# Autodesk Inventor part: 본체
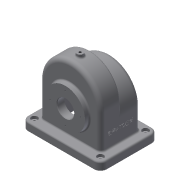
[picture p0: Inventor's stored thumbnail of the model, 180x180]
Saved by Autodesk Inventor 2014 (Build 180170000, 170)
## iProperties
Created: 2017-11
Part Number: 본체
Material: Generic
Document SubType Name: Modeling
Designer: user
Density: 1 g/cm^3
Appearance: Default
Author: user
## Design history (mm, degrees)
sketch "스케치1"
  geometry: L1 (-75, 55)-(75, 55); L2 (75, 55)-(75, -55); L3 (75, -55)-(-75, -55); L4 (-75, -55)-(-75, 55); L5 (-75, 55)-(75, -55); L6 (75, 55)-(-75, -55); 1 further point
  constraints: 12 end point, 2 midpoint, 2 parallel, 1 horizontal, 1 perpendicular
  dimensions: "d0" = 150 distance of L2.end L3.end; "d1" = 110 distance of L1.end L2.end
extrude "돌출1" new body sketch "스케치1" distance "d2" = 15; taper "d3" = 0 deg
sketch "스케치2"
  geometry: L1 (58, 0)-(-58, 0); L2 (-58, 0)-(-58, 80); L3 (-58, 80)-(58, 80); L4 (58, 80)-(58, 0); L5 (58, 0)-(-58, 80); L6 (-58, 0)-(58, 80); L7 (0, 0)-(0, 40); 1 further point
  constraints: 14 end point, 3 midpoint, 3 parallel, 1 horizontal, 1 perpendicular
  dimensions: "d5" = 116 distance of L2.end L3.end; "d6" = 80 distance of L1.end L2.end; "d7" = 40 distance of L7.end L7.start
extrude "돌출2" join sketch "스케치2" distance "d8" = 38; taper "d9" = 0 deg
sketch "스케치3"
  geometry: L1 (-58, 80)-(-58, 15) reference; L2 (0, 0)-(0, 28.5); L3 (58, 0)-(-58, 0); L4 (-58, 0)-(-58, 57); L5 (-58, 57)-(58, 57); L6 (58, 57)-(58, 0); L7 (58, 0)-(-58, 57); L8 (-58, 0)-(58, 57)
  constraints: 14 end point, 3 parallel, 2 midpoint, 1 horizontal, 1 perpendicular
  dimensions: "d10" = 28.5 distance of L2.start L2.end; "d11" = 116 distance of L4.end L5.end; "d12" = 57 distance of L3.end L4.end
extrude "돌출3" join sketch "스케치3" distance "d13" = 38; taper "d14" = 0 deg
sketch "스케치4"
  geometry: L1 (58, 80)-(-58, 80) reference; 2 further points
  constraints: 1 horizontal alignment, 1 midpoint, 2 other
extrude "돌출4" join sketch "스케치4" distance "d15" = 38; taper "d16" = 0 deg
sketch "스케치5"
  geometry: L1 (-58, 57)-(58, 57) reference; L2 (-75, 0)-(75, 0) reference; L3 (-10.724, 0)-(10.724, 0); A1 r 58 centre (0, 57) between (10.724, 0) and (-10.724, 0); 1 further point
  constraints: 3 point on circle, 2 end point, 2 point on line, 1 centre point, 1 collinear, 1 midpoint
extrude "돌출5" join sketch "스케치5" distance "d17" = 38; taper "d18" = 0 deg
sketch "스케치6"
  geometry: L1 (58, 15)-(58, 80) reference; L2 (0, 0)-(0, 65); C1 r 37.5 at (0, 65)
  constraints: 2 end point, 1 centre point, 1 coincident, 1 parallel
  dimensions: "d19" = 65 distance of L2.start L2.end; "d20" = 75 diameter of C1
extrude "돌출6" join sketch "스케치6" distance "d21" = 9; taper "d22" = 0 deg
sketch "스케치7"
  geometry: L1 (-58, 57)-(-58, 15) reference; L2 (0, 0)-(0, 65); C1 r 31 at (0, 65)
  constraints: 2 end point, 1 centre point, 1 coincident, 1 parallel
  dimensions: "d23" = 65 distance of L2.start L2.end; "d24" = 62 diameter of C1
extrude "돌출7" join sketch "스케치7" distance "d25" = 10; taper "d26" = 0 deg
sketch "스케치8"
  geometry: C1 r 37.5 at (0, 0) reference; C2 r 16 at (0, 0); 1 further point
  constraints: 1 centre point, 1 coincident
  dimensions: "d27" = 32 diameter of C2
extrude "돌출8" cut sketch "스케치8" distance "d28" = 95; taper "d29" = 0 deg
sketch "스케치9"
  geometry: L1 (53, -33)-(-53, -33); L2 (-53, -33)-(-53, 33); L3 (-53, 33)-(53, 33); L4 (53, 33)-(53, -33); L5 (53, -33)-(-53, 33); L6 (-53, -33)-(53, 33); 1 further point
  constraints: 12 end point, 2 midpoint, 2 parallel, 1 horizontal, 1 perpendicular
  dimensions: "d30" = 106 distance of L2.end L3.end; "d31" = 66 distance of L1.end L2.end
extrude "돌출9" cut sketch "스케치9" distance "d32" = 57; taper "d33" = 0 deg
sketch "스케치10"
  geometry: L1 (102.5, 47)-(27.5, 47) reference; L2 (57, 33)-(57, -33) reference; L3 (57, -33)-(57, 11.323); L4 (57, -33)-(110, -33); L5 (110, -33)-(110, 5); L6 (110, 5)-(57, 5); 1 further point
  constraints: 8 end point, 2 perpendicular, 2 point on line
  dimensions: "d34" = 53 distance of L2.end L4.end; "d35" = 38 distance of L4.end L5.end; "d36" = 53 distance of L5.end L6.end
revolve "회전1" sketch "스케치10" stored, may be unused: angle "d37" = 90 deg
sketch "스케치11"
  geometry: L1 (80, 38)-(138, 38) reference; L2 (138, 38)-(138, 0) reference; L3 (80, 38)-(85, 38); L4 (80, 33)-(133, 33); L5 (133, 33)-(133, 5); L6 (133, 5)-(80, 5); L7 (80, 33)-(80, 5); 1 further point
  constraints: 10 end point, 2 perpendicular, 1 horizontal, 1 parallel
  dimensions: "d39" = 5 distance of L1.start L4.start; "d41" = 53 distance of L4.start L4.end; "d42" = 28 distance of L4.end L5.end
revolve "회전2" sketch "스케치11" stored, may be unused: angle "d43" = 90 deg
sketch "스케치12"
  geometry: L1 (-53, -33)-(-53, 33) reference; L2 (-53, 33)-(53, 33) reference; L3 (-53, 5)-(-47.749, 5) reference; L4 (47.749, 33)-(47.749, 5) reference; L5 (47.749, 5)-(53, 5) reference; L6 (53, 33)-(53, 5) reference; L7 (47.749, 33)-(53, 33) reference; L8 (-47.749, 5)-(-47.749, 33) reference; L9 (-47.749, 5)-(-47.749, 33) reference; L10 (-53, 33)-(-47.749, 33) reference; L11 (-53, 5)-(-53, 33) reference; L12 (-53, 5)-(-47.749, 5) reference; 1 further point
extrude "돌출10" cut sketch "스케치12" distance "d44" = 80; taper "d45" = 0 deg
sketch "스케치13" dims "d46" = 58
  geometry: C1 r 37.5 at (0, 0) reference; C2 r 1.5 at (0, 29); C3 r 1.5 at (-29, 0); C4 r 1.5 at (0, -29); C5 r 1.5 at (29, 0); 5 further points
  constraints: 4 centre point, 4 coincident, 1 vertical alignment, 11 other
  dimensions: "d47" = 3 diameter of C2; "d50" = 360 deg dimension on point (0, 0) C2.centre (derived)
hole "구멍1" sketch "스케치13" at (0, 29), (-29, 0), (0, -29), (29, 0) diameter "d52" = 2.459; stored, may be unused: countersink angle "d56" = 90 deg, drill point angle "d58" = 118 deg; dims "d53" = 6, "d54" = 4, "d55" = 2, "d57" = 8
sketch "스케치14" dims "d59" = 52
  geometry: C1 r 31 at (0, 0) reference; C2 r 1.5 at (-26, 0); C3 r 1.5 at (0, -26); C4 r 1.5 at (26, 0); C5 r 1.5 at (0, 26); 2 further points
  constraints: 4 centre point, 1 coincident, 1 horizontal alignment, 11 other
  dimensions: "d60" = 3 diameter of C2; "d63" = 360 deg dimension on point (0, 0) C2.centre (derived)
hole "구멍2" sketch "스케치14" at (0, 26), (26, 0), (0, -26), (-26, 0) diameter "d65" = 2.459; stored, may be unused: countersink angle "d69" = 90 deg, drill point angle "d71" = 118 deg; dims "d66" = 6, "d67" = 4, "d68" = 2, "d70" = 8
fillet "모깎기1" dims "d72" = 12
sketch "스케치15"
  geometry: A1 r 12 centre (-63, 43) between (-63, 55) and (-75, 43) reference; A2 r 12 centre (-63, -43) between (-75, -43) and (-63, -55) reference; A3 r 12 centre (63, -43) between (63, -55) and (75, -43) reference; A4 r 12 centre (63, 43) between (75, 43) and (63, 55) reference; 1 further point
hole "구멍3" sketch "스케치15" at (-63, -43), (63, -43), (63, 43), (-63, 43) diameter "d73" = 5; stored, may be unused: countersink angle "d77" = 90 deg, drill point angle "d79" = 118 deg; dims "d74" = 6, "d75" = 12, "d76" = 5, "d78" = 8
node "작업 평면2"
sketch "스케치17"
  geometry: L1 (-58, 38)-(58, 38) reference; L2 (0, 38)-(0, 19); C1 r 6 at (0, 19); 1 further point
  constraints: 2 end point, 1 centre point, 1 coincident, 1 midpoint, 1 perpendicular
  dimensions: "d82" = 19 distance of L2.start L2.end; "d83" = 12 diameter of C1
extrude "돌출11" join sketch "스케치17" stored distance "d84" = 80; taper "d85" = 0 deg
sketch "스케치18"
  geometry: C1 r 6 at (0, 0) reference; 1 further point
hole "구멍4" sketch "스케치18" at (0, 0) diameter "d86" = 4.459; stored, may be unused: countersink angle "d90" = 90 deg, drill point angle "d92" = 118 deg; dims "d87" = 25, "d88" = 12, "d89" = 5, "d91" = 8
fillet "모깎기2" dims "d93" = 3
chamfer "모따기1" distance "d94" = 1; stored, may be unused: second distance "d95" = 2, angle "d96" = 45 deg
fillet "모깎기3" dims "d101" = 8
fillet "모깎기4" dims "d102" = 3
sketch "스케치20"
  geometry: L1 (-35, 23)-(-35, -39) reference; L2 (-40, -57)-(-52, -57) reference; 2 further points
  constraints: 1 other
  dimensions: "d103" = 38 distance from line of point (3, -17) L1; "d104" = 40 distance from line of L2 point (3, -17)
feature "엠보싱2" sketch "스케치20" dims "d0" = 150, "d1" = 110, "d10" = 28.5, "d11" = 116, "d12" = 57, "d105" = 0.5, "d106" = 0
node "솔리드1"
node "투영된 루프1"
node "투영된 루프2"
other parameters: "d81" = -144
